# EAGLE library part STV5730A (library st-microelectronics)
Multistandard ON-SCREEN DISPLAY for VCR, PAY-TV Satellite receiver
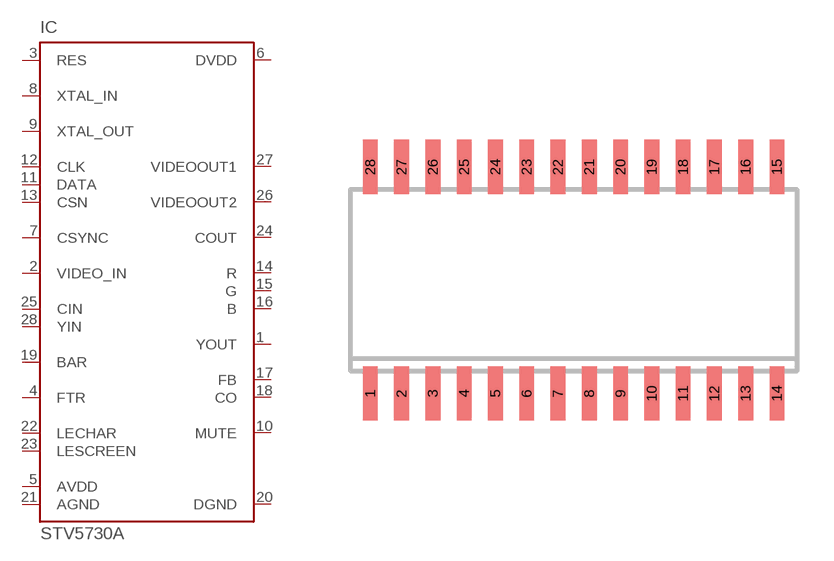
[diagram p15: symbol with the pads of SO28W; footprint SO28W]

Designator prefix IC

## STV5730A (OC_FARNELL: unknown; OC_NEWARK: unknown)  [SO28W]
1  YOUT  out
2  VIDEO_IN  in
3  RES  in
4  FTR  in
5  AVDD  pwr
6  DVDD  pwr
7  CSYNC
8  XTAL_IN  in
9  XTAL_OUT  out
10  MUTE  out
11  DATA  in
12  CLK  in
13  CSN  in
14  R  out
15  G  out
16  B  out
17  FB  out
18  CO  out
19  BAR  in
20  DGND  pwr
21  AGND  pwr
22  LECHAR  in
23  LESCREEN  in
24  COUT  out
25  CIN  in
26  VIDEOOUT2  out
27  VIDEOOUT1  out
28  YIN  in

## Footprint SO28W (pad centres in mm)
SMALL OUTLINE INTEGRATED CIRCUIT wide body 7.5 mm/JEDEC MO-119AB
smd 0.6 x 2.2: 1 -8.255,-4.6; 2 -6.985,-4.6; 3 -5.715,-4.6; 4 -4.445,-4.6; 5 -3.175,-4.6; 6 -1.905,-4.6; 7 -0.635,-4.6; 8 0.635,-4.6; 9 1.905,-4.6; 10 3.175,-4.6; 11 4.445,-4.6; 12 5.715,-4.6; 13 6.985,-4.6; 14 8.255,-4.6; 15 8.255,4.6; 16 6.985,4.6; 17 5.715,4.6; 18 4.445,4.6; 19 3.175,4.6; 20 1.905,4.6; 21 0.635,4.6; 22 -0.635,4.6; 23 -1.905,4.6; 24 -3.175,4.6; 25 -4.445,4.6; 26 -5.715,4.6; 27 -6.985,4.6; 28 -8.255,4.6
